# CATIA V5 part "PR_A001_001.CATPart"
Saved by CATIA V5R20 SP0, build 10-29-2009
Part number: PR_A001_001
Nomenclature: PR_A001_001
Source: bought
Description: Profilé 30x30xVariable
Bounding box of the stored display mesh (mm): x -15 to 15, y -15 to 15, z 0 to 670
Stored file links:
  C:\Users\halimelbaba\Documents\cmv\plan  d\PR_A001_001.CATPart
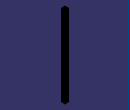
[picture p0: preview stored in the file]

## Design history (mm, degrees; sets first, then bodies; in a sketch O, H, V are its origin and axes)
Set1
  DatumCurve1
  Plane1: type Offset, RefPlane face of Solid1, Offset 0
  Sketch1 on Plane1, origin (0, 0, 900), H (1, 0, 0), V (0, -1, 0)
    line L1 (-15, 15) -> (15, 15)
    line L2 (15, 15) -> (15, -15)
    line L3 (15, -15) -> (-15, -15)
    line L4 (-15, -15) -> (-15, 15)
    reference projected line E1 (13, -15) -> (4.7, -15) from edge [face of Solid1 | face of Solid1]
    reference projected line E2 (15, -4.7) -> (15, -13) from edge [face of Solid1 | face of Solid1]
    reference projected line E3 (4.7, 15) -> (13, 15) from edge of DatumCurve2
    reference projected line E4 (-15, -13) -> (-15, -4.7) from edge [face of Solid1 | face of Solid1]
    horizontal: L1 H, L3 H
    vertical: L2 V, L4 V
    coincidence: L3 E1, L2 E2, L1 E3, L4 E4
  DatumCurve2
Body1 "MANIFOLD_SOLID_BREP #6353" (main body)
  Solid1: solid without history
  DatumSurface1
  Pocket1: profile Sketch1, direction (0, 0, -1), up to face of DatumSurface1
